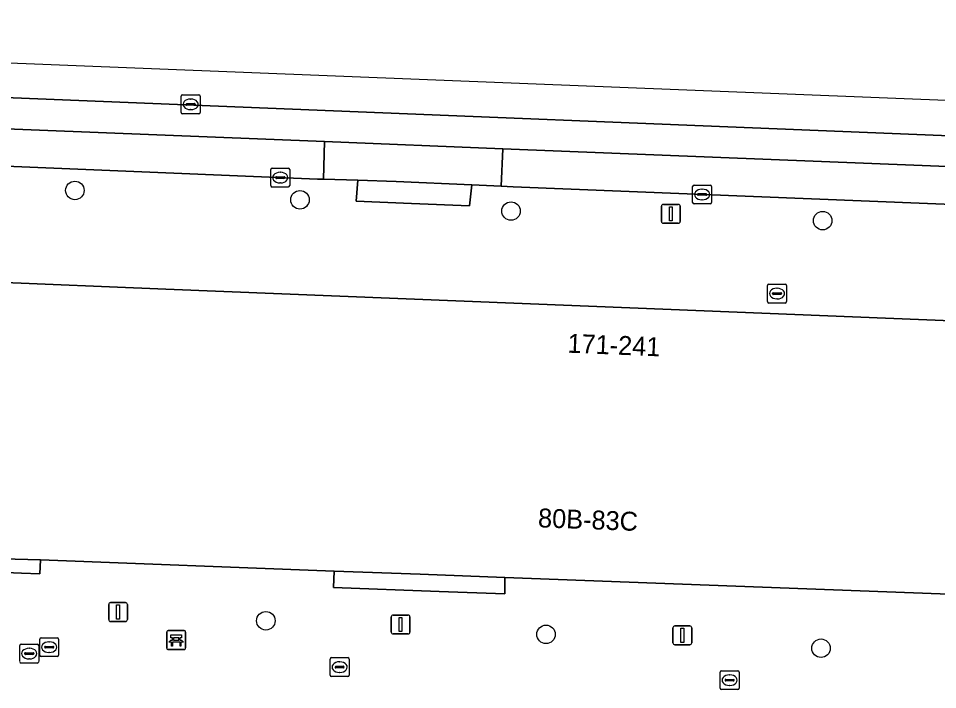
# Model space of a CAD drawing. Extents: x 160888 to 161385, y 386490 to 386908.
# Drawn here: x 161047.88 to 161096.46, y 386872.32 to 386907.8 of the extents above; entities that cross this region are included whole.
import ezdxf

# ---------------------------------------------------------------- set-up
doc = ezdxf.new("R2010")
doc.units = 0
for name, color, linetype in [('IMGEO_Bank', 7, 'Continuous'), ('IMGEO_Boom', 7, 'Continuous'), ('IMGEO_Kolk', 7, 'Continuous'), ('IMGEO_Lichtmast', 7, 'Continuous'), ('IMGEO_Pand', 7, 'Continuous'), ('IMGEO_Pand_nummerreeks', 7, 'Continuous'), ('IMGEO_Parkeervlak_gesloten', 7, 'Continuous'), ('IMGEO_Rijbaan_lokaal_gesloten', 7, 'Continuous'), ('IMGEO_Rioolput', 7, 'Continuous'), ('IMGEO_Voetpad_open', 7, 'Continuous')]:
    doc.layers.add(name, color=color, linetype=linetype)

msp = doc.modelspace()

# ---------------------------------------------------------------- linework, layer by layer
at = {"layer": 'IMGEO_Bank'}
for p, q in [((161055.721, 386874.513), (161055.721, 386875.354)), ((161055.721, 386875.354), (161055.721, 386874.513)), ((161055.796, 386875.438), (161056.637, 386875.438)), ((161056.637, 386875.438), (161055.796, 386875.438)), ((161056.721, 386875.363), (161056.721, 386874.522)), ((161056.721, 386874.522), (161056.721, 386875.363)), ((161056.418, 386874.836), (161056.025, 386874.836)), ((161056.03, 386874.944), (161056.03, 386875.05)), ((161056.074, 386875.05), (161056.074, 386874.944)), ((161056.362, 386875.056), (161056.08, 386875.056)), ((161056.08, 386874.938), (161056.362, 386874.938)), ((161056.368, 386874.944), (161056.368, 386875.05)), ((161056.412, 386875.05), (161056.412, 386874.944)), ((161056.646, 386874.438), (161055.805, 386874.438)), ((161055.805, 386874.438), (161056.646, 386874.438))]:
    msp.add_line(p, q, dxfattribs=at)
for points in [[(161056.024, 386875.056), (161055.938, 386875.056), (161055.938, 386875.217), (161056.501, 386875.217), (161056.501, 386875.056), (161056.418, 386875.056)], [(161055.968, 386874.836), (161055.826, 386874.836), (161055.938, 386874.938), (161056.024, 386874.938)], [(161056.018, 386874.829), (161056.018, 386874.622), (161055.975, 386874.622), (161055.975, 386874.829)], [(161056.418, 386874.938), (161056.501, 386874.938), (161056.613, 386874.836), (161056.474, 386874.836)], [(161056.468, 386874.829), (161056.468, 386874.622), (161056.424, 386874.622), (161056.424, 386874.829)]]:
    msp.add_lwpolyline(points, dxfattribs=at)
for centre, radius, start, end in [((161055.799, 386875.36), 0.0779, 92.4484, 184.2845), ((161055.799, 386875.36), 0.0779, 92.4484, 184.2845), ((161056.643, 386875.36), 0.0779, 2.4484, 94.2845), ((161056.643, 386875.36), 0.0779, 2.4484, 94.2845), ((161055.968, 386874.829), 0.00671, 2.8957, 87.1043), ((161056.025, 386874.829), 0.00671, 92.8957, 177.1043), ((161056.023, 386875.049), 0.00671, 2.8957, 87.1043), ((161056.023, 386874.945), 0.00671, 272.8957, 357.1043), ((161056.08, 386875.049), 0.00671, 92.8957, 177.1043), ((161056.08, 386874.945), 0.00671, 182.8957, 267.1043), ((161056.362, 386875.049), 0.00671, 2.8957, 87.1043), ((161056.362, 386874.945), 0.00671, 272.8957, 357.1043), ((161056.419, 386875.049), 0.00671, 92.8957, 177.1043), ((161056.419, 386874.945), 0.00671, 182.8957, 267.1043), ((161056.417, 386874.829), 0.00671, 2.8957, 87.1043), ((161056.474, 386874.829), 0.00671, 92.8957, 177.1043), ((161055.799, 386874.516), 0.0779, 182.4484, 274.2845), ((161055.799, 386874.516), 0.0779, 182.4484, 274.2845), ((161056.643, 386874.516), 0.0779, 272.4484, 4.2845), ((161056.643, 386874.516), 0.0779, 272.4484, 4.2845)]:
    msp.add_arc(centre, radius, start, end, dxfattribs=at)
at = {"layer": 'IMGEO_Boom'}
for centre in [(161050.866, 386898.705), (161062.764, 386898.21), (161073.919, 386897.615), (161090.388, 386897.109), (161060.96, 386875.958), (161075.769, 386875.241), (161090.302, 386874.507)]:
    msp.add_circle(centre, 0.489, dxfattribs=at)
at = {"layer": 'IMGEO_Kolk'}
for p, q in [((161061.296, 386899.884), (161062.148, 386899.884)), ((161061.221, 386898.958), (161061.221, 386899.81)), ((161061.48, 386899.378), (161061.48, 386899.39)), ((161061.523, 386899.427), (161061.921, 386899.427)), ((161061.709, 386899.664), (161061.734, 386899.664)), ((161061.964, 386899.39), (161061.964, 386899.378)), ((161062.222, 386899.81), (161062.222, 386898.958)), ((161061.918, 386899.341), (161061.52, 386899.341)), ((161061.732, 386899.104), (161061.707, 386899.104)), ((161083.515, 386898.066), (161083.515, 386898.918)), ((161083.59, 386898.992), (161084.442, 386898.992)), ((161084.516, 386898.918), (161084.516, 386898.066)), ((161062.148, 386898.884), (161061.296, 386898.884)), ((161083.774, 386898.486), (161083.774, 386898.498)), ((161084.212, 386898.449), (161083.814, 386898.449)), ((161083.817, 386898.535), (161084.215, 386898.535)), ((161084.003, 386898.772), (161084.028, 386898.772)), ((161084.258, 386898.498), (161084.258, 386898.486)), ((161084.442, 386897.992), (161083.59, 386897.992)), ((161084.026, 386898.212), (161084.001, 386898.212)), ((161047.954, 386873.797), (161047.954, 386874.649)), ((161048.029, 386874.723), (161048.881, 386874.723)), ((161048.955, 386874.649), (161048.955, 386873.797)), ((161048.213, 386874.217), (161048.213, 386874.229)), ((161048.651, 386874.18), (161048.253, 386874.18)), ((161048.256, 386874.266), (161048.654, 386874.266)), ((161048.442, 386874.503), (161048.467, 386874.503)), ((161048.697, 386874.229), (161048.697, 386874.217)), ((161048.881, 386873.723), (161048.029, 386873.723)), ((161048.465, 386873.943), (161048.44, 386873.943)), ((161064.36, 386873.083), (161064.36, 386873.935)), ((161064.435, 386874.009), (161065.287, 386874.009)), ((161064.848, 386873.789), (161064.873, 386873.789)), ((161065.361, 386873.935), (161065.361, 386873.083)), ((161064.619, 386873.503), (161064.619, 386873.515)), ((161065.057, 386873.466), (161064.659, 386873.466)), ((161064.662, 386873.552), (161065.06, 386873.552)), ((161064.871, 386873.229), (161064.846, 386873.229)), ((161065.103, 386873.515), (161065.103, 386873.503)), ((161084.97, 386872.394), (161084.97, 386873.246)), ((161085.045, 386873.32), (161085.897, 386873.32)), ((161085.971, 386873.246), (161085.971, 386872.394)), ((161065.287, 386873.009), (161064.435, 386873.009)), ((161085.229, 386872.814), (161085.229, 386872.826)), ((161085.667, 386872.777), (161085.269, 386872.777)), ((161085.272, 386872.863), (161085.67, 386872.863)), ((161085.458, 386873.1), (161085.483, 386873.1)), ((161085.713, 386872.826), (161085.713, 386872.814)), ((161085.897, 386872.32), (161085.045, 386872.32)), ((161085.481, 386872.54), (161085.456, 386872.54))]:
    msp.add_line(p, q, dxfattribs=at)
for points in [[(161061.296, 386899.884), (161062.148, 386899.884)], [(161061.221, 386898.958), (161061.221, 386899.81)], [(161062.222, 386899.81), (161062.222, 386898.958)], [(161083.515, 386898.066), (161083.515, 386898.918)], [(161083.59, 386898.992), (161084.442, 386898.992)], [(161084.516, 386898.918), (161084.516, 386898.066)], [(161062.148, 386898.884), (161061.296, 386898.884)], [(161084.442, 386897.992), (161083.59, 386897.992)], [(161047.954, 386873.797), (161047.954, 386874.649)], [(161048.029, 386874.723), (161048.881, 386874.723)], [(161048.955, 386874.649), (161048.955, 386873.797)], [(161048.881, 386873.723), (161048.029, 386873.723)], [(161064.36, 386873.083), (161064.36, 386873.935)], [(161064.435, 386874.009), (161065.287, 386874.009)], [(161065.361, 386873.935), (161065.361, 386873.083)], [(161084.97, 386872.394), (161084.97, 386873.246)], [(161085.045, 386873.32), (161085.897, 386873.32)], [(161085.971, 386873.246), (161085.971, 386872.394)], [(161065.287, 386873.009), (161064.435, 386873.009)], [(161085.897, 386872.32), (161085.045, 386872.32)]]:
    msp.add_lwpolyline(points, dxfattribs=at)
for centre, radius, start, end in [((161061.298, 386899.808), 0.0765, 91.552, 178.448), ((161061.298, 386899.808), 0.0765, 91.552, 178.448), ((161062.146, 386899.808), 0.0765, 1.552, 88.448), ((161062.146, 386899.808), 0.0765, 1.552, 88.448), ((161061.52, 386899.387), 0.0403, 85.8775, 175.7526), ((161061.925, 386899.389), 0.0386, 1.7309, 96.639), ((161061.298, 386898.96), 0.0765, 181.552, 268.448), ((161061.298, 386898.96), 0.0765, 181.552, 268.448), ((161061.517, 386899.377), 0.0366, 178.938, 274.7102), ((161061.921, 386899.384), 0.043, 264.8664, 352.4533), ((161062.146, 386898.96), 0.0765, 271.552, 358.448), ((161062.146, 386898.96), 0.0765, 271.552, 358.448), ((161083.592, 386898.916), 0.0765, 91.552, 178.448), ((161083.592, 386898.916), 0.0765, 91.552, 178.448), ((161084.44, 386898.916), 0.0765, 1.552, 88.448), ((161084.44, 386898.916), 0.0765, 1.552, 88.448), ((161083.814, 386898.495), 0.0403, 85.8775, 175.7526), ((161083.811, 386898.485), 0.0366, 178.938, 274.7102), ((161084.215, 386898.492), 0.043, 264.8664, 352.4533), ((161084.219, 386898.497), 0.0386, 1.7309, 96.639), ((161083.592, 386898.068), 0.0765, 181.552, 268.448), ((161083.592, 386898.068), 0.0765, 181.552, 268.448), ((161084.44, 386898.068), 0.0765, 271.552, 358.448), ((161084.44, 386898.068), 0.0765, 271.552, 358.448), ((161048.031, 386874.647), 0.0765, 91.552, 178.448), ((161048.031, 386874.647), 0.0765, 91.552, 178.448), ((161048.879, 386874.647), 0.0765, 1.552, 88.448), ((161048.879, 386874.647), 0.0765, 1.552, 88.448), ((161048.253, 386874.226), 0.0403, 85.8775, 175.7526), ((161048.25, 386874.216), 0.0366, 178.938, 274.7102), ((161048.654, 386874.223), 0.043, 264.8664, 352.4533), ((161048.658, 386874.228), 0.0386, 1.7309, 96.639), ((161048.031, 386873.799), 0.0765, 181.552, 268.448), ((161048.031, 386873.799), 0.0765, 181.552, 268.448), ((161048.879, 386873.799), 0.0765, 271.552, 358.448), ((161048.879, 386873.799), 0.0765, 271.552, 358.448), ((161064.437, 386873.933), 0.0765, 91.552, 178.448), ((161064.437, 386873.933), 0.0765, 91.552, 178.448), ((161065.285, 386873.933), 0.0765, 1.552, 88.448), ((161065.285, 386873.933), 0.0765, 1.552, 88.448), ((161064.659, 386873.512), 0.0403, 85.8775, 175.7526), ((161064.656, 386873.502), 0.0366, 178.938, 274.7102), ((161065.06, 386873.509), 0.043, 264.8664, 352.4533), ((161065.064, 386873.514), 0.0386, 1.7309, 96.639), ((161085.047, 386873.244), 0.0765, 91.552, 178.448), ((161085.047, 386873.244), 0.0765, 91.552, 178.448), ((161085.895, 386873.244), 0.0765, 1.552, 88.448), ((161085.895, 386873.244), 0.0765, 1.552, 88.448), ((161064.437, 386873.085), 0.0765, 181.552, 268.448), ((161064.437, 386873.085), 0.0765, 181.552, 268.448), ((161065.285, 386873.085), 0.0765, 271.552, 358.448), ((161065.285, 386873.085), 0.0765, 271.552, 358.448), ((161085.269, 386872.823), 0.0403, 85.8775, 175.7526), ((161085.266, 386872.813), 0.0366, 178.938, 274.7102), ((161085.67, 386872.82), 0.043, 264.8664, 352.4533), ((161085.674, 386872.825), 0.0386, 1.7309, 96.639), ((161085.047, 386872.396), 0.0765, 181.552, 268.448), ((161085.047, 386872.396), 0.0765, 181.552, 268.448), ((161085.895, 386872.396), 0.0765, 271.552, 358.448), ((161085.895, 386872.396), 0.0765, 271.552, 358.448)]:
    msp.add_arc(centre, radius, start, end, dxfattribs=at)
for centre, major_axis, ratio, start_param, end_param in [((161061.708, 386899.384), (-0.387, 0.002), 0.722429, 4.712389, 7.853982), ((161061.733, 386899.384), (-0.39, 0.002), 0.717154, 1.570796, 4.712389), ((161084.002, 386898.492), (-0.387, 0.002), 0.722429, 4.712389, 7.853982), ((161084.027, 386898.492), (-0.39, 0.002), 0.717154, 1.570796, 4.712389), ((161048.441, 386874.223), (-0.387, 0.002), 0.722429, 4.712389, 7.853982), ((161048.466, 386874.223), (-0.39, 0.002), 0.717154, 1.570796, 4.712389), ((161064.847, 386873.509), (-0.387, 0.002), 0.722429, 4.712389, 7.853982), ((161064.872, 386873.509), (-0.39, 0.002), 0.717154, 1.570796, 4.712389), ((161085.457, 386872.82), (-0.387, 0.002), 0.722429, 4.712389, 7.853982), ((161085.482, 386872.82), (-0.39, 0.002), 0.717154, 1.570796, 4.712389)]:
    msp.add_ellipse(centre, major_axis=major_axis, ratio=ratio, start_param=start_param, end_param=end_param, dxfattribs=at)
at = {"layer": 'IMGEO_Lichtmast'}
for p, q in [((161081.968, 386897.969), (161082.758, 386897.969)), ((161082.758, 386897.969), (161081.968, 386897.969)), ((161081.868, 386897.069), (161081.868, 386897.869)), ((161081.868, 386897.869), (161081.868, 386897.069)), ((161082.858, 386897.869), (161082.858, 386897.069)), ((161082.858, 386897.069), (161082.858, 386897.869)), ((161082.758, 386896.969), (161081.968, 386896.969)), ((161081.968, 386896.969), (161082.758, 386896.969)), ((161052.654, 386876.021), (161052.654, 386876.821)), ((161052.654, 386876.821), (161052.654, 386876.021)), ((161052.754, 386876.921), (161053.544, 386876.921)), ((161053.544, 386876.921), (161052.754, 386876.921)), ((161053.644, 386876.821), (161053.644, 386876.021)), ((161053.644, 386876.021), (161053.644, 386876.821)), ((161067.584, 386875.362), (161067.584, 386876.162)), ((161067.584, 386876.162), (161067.584, 386875.362)), ((161067.684, 386876.262), (161068.474, 386876.262)), ((161068.474, 386876.262), (161067.684, 386876.262)), ((161068.574, 386876.162), (161068.574, 386875.362)), ((161068.574, 386875.362), (161068.574, 386876.162)), ((161053.544, 386875.921), (161052.754, 386875.921)), ((161052.754, 386875.921), (161053.544, 386875.921)), ((161082.475, 386874.788), (161082.475, 386875.588)), ((161082.475, 386875.588), (161082.475, 386874.788)), ((161082.575, 386875.688), (161083.365, 386875.688)), ((161083.365, 386875.688), (161082.575, 386875.688)), ((161083.465, 386875.588), (161083.465, 386874.788)), ((161083.465, 386874.788), (161083.465, 386875.588)), ((161068.474, 386875.262), (161067.684, 386875.262)), ((161067.684, 386875.262), (161068.474, 386875.262)), ((161083.365, 386874.688), (161082.575, 386874.688)), ((161082.575, 386874.688), (161083.365, 386874.688))]:
    msp.add_line(p, q, dxfattribs=at)
for points in [[(161082.288, 386897.844), (161082.438, 386897.844), (161082.438, 386897.094), (161082.288, 386897.094), (161082.288, 386897.844)], [(161053.074, 386876.796), (161053.224, 386876.796), (161053.224, 386876.046), (161053.074, 386876.046), (161053.074, 386876.796)], [(161068.004, 386876.137), (161068.154, 386876.137), (161068.154, 386875.387), (161068.004, 386875.387), (161068.004, 386876.137)], [(161082.895, 386875.563), (161083.045, 386875.563), (161083.045, 386874.813), (161082.895, 386874.813), (161082.895, 386875.563)]]:
    msp.add_lwpolyline(points, dxfattribs=at)
for centre, start, end in [((161081.968, 386897.869), 90, 180), ((161081.968, 386897.869), 90, 180), ((161082.758, 386897.869), 0, 90), ((161082.758, 386897.869), 360, 90), ((161081.968, 386897.069), 180, 270), ((161081.968, 386897.069), 180, 270), ((161082.758, 386897.069), 270, 0), ((161082.758, 386897.069), 270, 0), ((161052.754, 386876.821), 90, 180), ((161052.754, 386876.821), 90, 180), ((161053.544, 386876.821), 0, 90), ((161053.544, 386876.821), 360, 90), ((161067.684, 386876.162), 90, 180), ((161067.684, 386876.162), 90, 180), ((161068.474, 386876.162), 0, 90), ((161068.474, 386876.162), 360, 90), ((161052.754, 386876.021), 180, 270), ((161052.754, 386876.021), 180, 270), ((161053.544, 386876.021), 270, 0), ((161053.544, 386876.021), 270, 0), ((161082.575, 386875.588), 90, 180), ((161082.575, 386875.588), 90, 180), ((161083.365, 386875.588), 0, 90), ((161083.365, 386875.588), 360, 90), ((161067.684, 386875.362), 180, 270), ((161067.684, 386875.362), 180, 270), ((161068.474, 386875.362), 270, 0), ((161068.474, 386875.362), 270, 0), ((161082.575, 386874.788), 180, 270), ((161082.575, 386874.788), 180, 270), ((161083.365, 386874.788), 270, 0), ((161083.365, 386874.788), 270, 0)]:
    msp.add_arc(centre, 0.1, start, end, dxfattribs=at)
at = {"layer": 'IMGEO_Pand'}
msp.add_lwpolyline([(161113.143, 386891.17), (161097.194, 386891.813), (161080.645, 386892.481), (161055.667, 386893.489), (161046.293, 386893.867), (161046.299, 386893.997), (161046.043, 386894.008), (161045.711, 386885.882), (161045.442, 386879.308), (161047.716, 386879.222), (161049.049, 386879.172), (161064.569, 386878.588), (161069.116, 386878.417), (161073.594, 386878.249), (161112.563, 386876.783), (161112.919, 386885.615)], close=True, dxfattribs=at)
at = {"layer": 'IMGEO_Parkeervlak_gesloten'}
msp.add_lwpolyline([(161064.059, 386901.284), (161040.12, 386902.25), (161040.028, 386900.281), (161063.696, 386899.307), (161064.015, 386899.299)], close=True, dxfattribs=at)
msp.add_lwpolyline([(161112.234, 386899.353), (161109.397, 386899.476), (161073.486, 386900.908), (161073.403, 386898.925), (161074.03, 386898.891), (161108.628, 386897.506), (161109.298, 386897.46), (161109.361, 386897.456)], dxfattribs=at)
at = {"layer": 'IMGEO_Rijbaan_lokaal_gesloten'}
for points in [[(161112.38, 386902.848), (160988.148, 386907.8), (160987.595, 386907.148)], [(160986.431, 386905.776), (160986.431, 386905.776), (160987.414, 386904.997), (160988.842, 386904.061), (160989.598, 386903.645), (160992.187, 386902.648), (160994.092, 386902.091), (160996.449, 386901.746), (160999.189, 386901.61), (161000, 386901.579), (161012.233, 386901.108), (161035.324, 386900.473), (161035.479, 386900.468), (161040.028, 386900.281), (161040.12, 386902.25), (161064.059, 386901.284), (161073.486, 386900.908), (161109.397, 386899.476), (161112.234, 386899.353), (161112.299, 386900.982), (161040.205, 386903.901), (161035.665, 386902.345), (160996.157, 386903.935)], [(160996.157, 386903.935), (161035.665, 386902.345), (161040.205, 386903.901), (161112.299, 386900.982), (161112.38, 386902.848)]]:
    msp.add_lwpolyline(points, dxfattribs=at)
msp.add_lwpolyline([(161073.486, 386900.908), (161064.059, 386901.284), (161064.015, 386899.299), (161065.827, 386899.252), (161067.845, 386899.171), (161071.838, 386899.01), (161073.403, 386898.925)], close=True, dxfattribs=at)
at = {"layer": 'IMGEO_Rioolput'}
for p, q in [((161056.561, 386903.757), (161057.413, 386903.757)), ((161056.486, 386902.831), (161056.486, 386903.683)), ((161056.788, 386903.3), (161057.186, 386903.3)), ((161056.974, 386903.537), (161056.999, 386903.537)), ((161057.487, 386903.683), (161057.487, 386902.831)), ((161056.745, 386903.251), (161056.745, 386903.263)), ((161057.183, 386903.214), (161056.785, 386903.214)), ((161056.997, 386902.977), (161056.972, 386902.977)), ((161057.229, 386903.263), (161057.229, 386903.251)), ((161057.413, 386902.757), (161056.561, 386902.757)), ((161087.475, 386892.828), (161087.475, 386893.68)), ((161087.55, 386893.754), (161088.402, 386893.754)), ((161088.476, 386893.68), (161088.476, 386892.828)), ((161087.734, 386893.248), (161087.734, 386893.26)), ((161088.172, 386893.211), (161087.774, 386893.211)), ((161087.777, 386893.297), (161088.175, 386893.297)), ((161087.963, 386893.534), (161087.988, 386893.534)), ((161088.218, 386893.26), (161088.218, 386893.248)), ((161088.402, 386892.754), (161087.55, 386892.754)), ((161087.986, 386892.974), (161087.961, 386892.974)), ((161049.008, 386874.138), (161049.008, 386874.99)), ((161049.083, 386875.064), (161049.935, 386875.064)), ((161049.496, 386874.844), (161049.521, 386874.844)), ((161050.009, 386874.99), (161050.009, 386874.138)), ((161049.267, 386874.558), (161049.267, 386874.57)), ((161049.705, 386874.521), (161049.307, 386874.521)), ((161049.31, 386874.607), (161049.708, 386874.607)), ((161049.519, 386874.284), (161049.494, 386874.284)), ((161049.751, 386874.57), (161049.751, 386874.558)), ((161049.935, 386874.064), (161049.083, 386874.064))]:
    msp.add_line(p, q, dxfattribs=at)
for points in [[(161056.561, 386903.757), (161057.413, 386903.757)], [(161056.486, 386902.831), (161056.486, 386903.683)], [(161057.487, 386903.683), (161057.487, 386902.831)], [(161057.413, 386902.757), (161056.561, 386902.757)], [(161087.475, 386892.828), (161087.475, 386893.68)], [(161087.55, 386893.754), (161088.402, 386893.754)], [(161088.476, 386893.68), (161088.476, 386892.828)], [(161088.402, 386892.754), (161087.55, 386892.754)], [(161049.008, 386874.138), (161049.008, 386874.99)], [(161049.083, 386875.064), (161049.935, 386875.064)], [(161050.009, 386874.99), (161050.009, 386874.138)], [(161049.935, 386874.064), (161049.083, 386874.064)]]:
    msp.add_lwpolyline(points, dxfattribs=at)
for centre, radius, start, end in [((161056.563, 386903.681), 0.0765, 91.552, 178.448), ((161056.563, 386903.681), 0.0765, 91.552, 178.448), ((161057.411, 386903.681), 0.0765, 1.552, 88.448), ((161057.411, 386903.681), 0.0765, 1.552, 88.448), ((161056.785, 386903.26), 0.0403, 85.8775, 175.7526), ((161057.19, 386903.262), 0.0386, 1.7309, 96.639), ((161056.563, 386902.833), 0.0765, 181.552, 268.448), ((161056.563, 386902.833), 0.0765, 181.552, 268.448), ((161056.782, 386903.25), 0.0366, 178.938, 274.7102), ((161057.186, 386903.257), 0.043, 264.8664, 352.4533), ((161057.411, 386902.833), 0.0765, 271.552, 358.448), ((161057.411, 386902.833), 0.0765, 271.552, 358.448), ((161087.552, 386893.678), 0.0765, 91.552, 178.448), ((161087.552, 386893.678), 0.0765, 91.552, 178.448), ((161088.4, 386893.678), 0.0765, 1.552, 88.448), ((161088.4, 386893.678), 0.0765, 1.552, 88.448), ((161087.774, 386893.257), 0.0403, 85.8775, 175.7526), ((161087.771, 386893.247), 0.0366, 178.938, 274.7102), ((161088.175, 386893.254), 0.043, 264.8664, 352.4533), ((161088.179, 386893.259), 0.0386, 1.7309, 96.639), ((161087.552, 386892.83), 0.0765, 181.552, 268.448), ((161087.552, 386892.83), 0.0765, 181.552, 268.448), ((161088.4, 386892.83), 0.0765, 271.552, 358.448), ((161088.4, 386892.83), 0.0765, 271.552, 358.448), ((161049.085, 386874.988), 0.0765, 91.552, 178.448), ((161049.085, 386874.988), 0.0765, 91.552, 178.448), ((161049.712, 386874.569), 0.0386, 1.7309, 96.639), ((161049.933, 386874.988), 0.0765, 1.552, 88.448), ((161049.933, 386874.988), 0.0765, 1.552, 88.448), ((161049.085, 386874.14), 0.0765, 181.552, 268.448), ((161049.085, 386874.14), 0.0765, 181.552, 268.448), ((161049.307, 386874.567), 0.0403, 85.8775, 175.7526), ((161049.304, 386874.557), 0.0366, 178.938, 274.7102), ((161049.708, 386874.564), 0.043, 264.8664, 352.4533), ((161049.933, 386874.14), 0.0765, 271.552, 358.448), ((161049.933, 386874.14), 0.0765, 271.552, 358.448)]:
    msp.add_arc(centre, radius, start, end, dxfattribs=at)
for centre, major_axis, ratio, start_param, end_param in [((161056.973, 386903.257), (-0.387, 0.002), 0.722429, 4.712389, 7.853982), ((161056.998, 386903.257), (-0.39, 0.002), 0.717154, 1.570796, 4.712389), ((161087.962, 386893.254), (-0.387, 0.002), 0.722429, 4.712389, 7.853982), ((161087.987, 386893.254), (-0.39, 0.002), 0.717154, 1.570796, 4.712389), ((161049.495, 386874.564), (-0.387, 0.002), 0.722429, 4.712389, 7.853982), ((161049.52, 386874.564), (-0.39, 0.002), 0.717154, 1.570796, 4.712389)]:
    msp.add_ellipse(centre, major_axis=major_axis, ratio=ratio, start_param=start_param, end_param=end_param, dxfattribs=at)
at = {"layer": 'IMGEO_Voetpad_open'}
for points in [[(160986.001, 386902.936), (160981.133, 386897.248), (160982.853, 386895.847), (160984.295, 386894.643), (160993.236, 386896.016), (161004.65, 386895.537), (161029.981, 386894.476), (161035.955, 386894.217), (161041.701, 386893.968), (161046.043, 386894.008), (161046.299, 386893.997), (161046.293, 386893.867), (161055.667, 386893.489), (161080.645, 386892.481), (161097.194, 386891.813), (161113.143, 386891.17), (161127.058, 386890.969), (161178.427, 386888.94)], [(161109.361, 386897.456), (161109.298, 386897.46), (161108.628, 386897.506), (161074.03, 386898.891), (161073.403, 386898.925), (161071.838, 386899.01), (161071.724, 386897.893), (161068.662, 386898.016), (161065.732, 386898.135), (161065.827, 386899.252), (161064.015, 386899.299), (161063.696, 386899.307), (161040.028, 386900.281), (161035.479, 386900.468), (161035.324, 386900.473)], [(161119.79, 386888.855), (161126.941, 386888.577), (161127.058, 386890.969), (161113.143, 386891.17), (161112.919, 386885.615), (161112.563, 386876.783), (161073.594, 386878.249), (161073.583, 386877.375), (161070.12, 386877.508), (161064.537, 386877.72), (161064.569, 386878.588), (161049.049, 386879.172), (161049.023, 386878.446), (161048.048, 386878.482), (161045.473, 386878.577)]]:
    msp.add_lwpolyline(points, dxfattribs=at)
for points in [[(161065.827, 386899.252), (161065.732, 386898.135), (161068.662, 386898.016), (161071.724, 386897.893), (161071.838, 386899.01), (161067.845, 386899.171)], [(161045.473, 386878.577), (161048.048, 386878.482), (161049.023, 386878.446), (161049.049, 386879.172), (161047.716, 386879.222), (161045.442, 386879.308)], [(161064.537, 386877.72), (161070.12, 386877.508), (161073.583, 386877.375), (161073.594, 386878.249), (161069.116, 386878.417), (161064.569, 386878.588)]]:
    msp.add_lwpolyline(points, close=True, dxfattribs=at)

# ---------------------------------------------------------------- texts
at = {"layer": 'IMGEO_Pand_nummerreeks'}
for s, rotation, p in [('171-241', 357.691, (161076.887, 386890.131)), ('80B-83C', 357.8629, (161075.332, 386880.902))]:
    msp.add_text(s, height=1, rotation=rotation, dxfattribs=at).set_placement(p)

doc.saveas('drawing.dxf')
